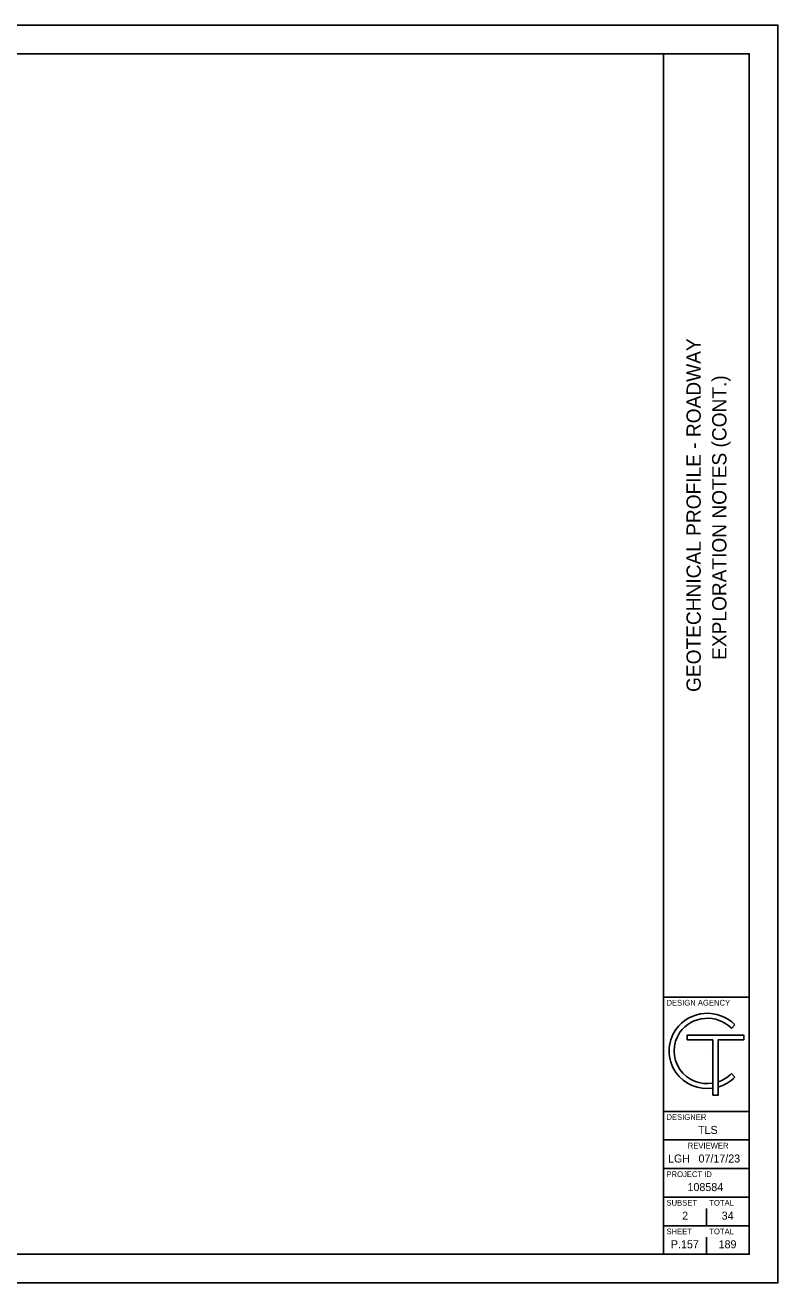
# Model space of a CAD drawing. Extents: x 0 to 34, y 0 to 22.
# Drawn here: x 20.82 to 34, y 0 to 22 of the extents above; entities that cross this region are included whole.
import ezdxf

# ---------------------------------------------------------------- set-up
doc = ezdxf.new("R2010")
doc.units = 0
for name, color, linetype in [('SH_Border', 7, 'Continuous'), ('SH_Cut_Line', 7, 'Continuous'), ('SH_Data', 7, 'Continuous'), ('SH_Text', 7, 'Continuous')]:
    doc.layers.add(name, color=color, linetype=linetype)

msp = doc.modelspace()

# ---------------------------------------------------------------- linework, layer by layer
at = {"layer": 'SH_Border'}
for p, q in [((32, 0.5), (32, 21.5)), ((32, 5), (33.5, 5)), ((32, 3), (33.5, 3)), ((32, 2.5), (33.5, 2.5)), ((32, 2), (33.5, 2)), ((32, 1.5), (33.5, 1.5)), ((32, 1), (33.5, 1))]:
    msp.add_line(p, q, dxfattribs=at)
msp.add_lwpolyline([(1.5, 21.5), (33.5, 21.5), (33.5, 0.5), (1.5, 0.5)], close=True, dxfattribs=at)
at = {"layer": 'SH_Cut_Line'}
msp.add_lwpolyline([(0, 0), (34, 0), (34, 22), (0, 22)], close=True, dxfattribs=at)
at = {"layer": 'SH_Data'}
for p, q in [((32.75, 4), (32.75, 4)), ((32.75, 1), (32.75, 1.3)), ((32.375, 0.675), (32.375, 0.675)), ((32.75, 0.5), (32.75, 0.8))]:
    msp.add_line(p, q, dxfattribs=at)
at = {"layer": 'SH_Text'}
for p, q in [((33.249, 4.513), (33.187, 4.452)), ((33.249, 4.513), (33.187, 4.452)), ((33.402, 4.333), (32.414, 4.333)), ((32.414, 4.333), (32.414, 4.251)), ((32.414, 4.251), (32.863, 4.251)), ((32.863, 4.251), (32.863, 3.285)), ((32.956, 3.285), (32.956, 4.251)), ((32.956, 4.251), (33.402, 4.251)), ((33.402, 4.251), (33.402, 4.333)), ((33.187, 3.66), (33.249, 3.599)), ((33.187, 3.66), (33.249, 3.599)), ((32.863, 3.493), (32.863, 3.405)), ((32.863, 3.493), (32.863, 3.405)), ((32.956, 3.425), (32.956, 3.516)), ((32.956, 3.425), (32.956, 3.516)), ((32.863, 3.285), (32.956, 3.285))]:
    msp.add_line(p, q, dxfattribs=at)
msp.add_lwpolyline([(32.863, 4.251), (32.863, 3.285), (32.956, 3.285), (32.956, 4.251), (33.402, 4.251), (33.402, 4.333), (32.414, 4.333), (32.414, 4.251)], close=True, dxfattribs=at)
for centre, radius, start, end in [((32.766, 4.035), 0.68, 44.7027, 144.3276), ((32.766, 4.035), 0.68, 44.7027, 144.3276), ((32.766, 4.035), 0.593, 44.7362, 144.1102), ((32.766, 4.035), 0.593, 44.7362, 144.1102), ((32.764, 4.056), 0.666, 145.7329, 214.2671), ((32.764, 4.056), 0.666, 145.7329, 214.2671), ((32.764, 4.056), 0.579, 145.7266, 214.2734), ((32.764, 4.056), 0.579, 145.7266, 214.2734), ((32.766, 4.078), 0.68, 215.6724, 278.2613), ((32.766, 4.078), 0.68, 215.6724, 278.2613), ((32.766, 4.078), 0.593, 215.8898, 279.4882), ((32.766, 4.078), 0.593, 215.8898, 279.4882), ((32.766, 4.078), 0.593, 288.6992, 315.2638), ((32.766, 4.078), 0.593, 288.6992, 315.2638), ((32.766, 4.078), 0.68, 286.2291, 315.2973), ((32.766, 4.078), 0.68, 286.2291, 315.2973)]:
    msp.add_arc(centre, radius, start, end, dxfattribs=at)

# ---------------------------------------------------------------- texts
at = {"layer": 'SH_Data'}
for s, p in [('GEOTECHNICAL PROFILE - ROADWAY', (32.65, 10.336)), ('EXPLORATION NOTES (CONT.)', (33.1, 10.897))]:
    msp.add_text(s, height=0.25, rotation=90, dxfattribs=at).set_placement(p)
for s, height, p in [('DESIGN AGENCY', 0.1, (32.05, 4.85)), ('DESIGNER', 0.1, (32.05, 2.85)), ('TLS', 0.14, (32.603, 2.605)), ('REVIEWER', 0.1, (32.422, 2.35)), ('LGH', 0.14, (32.077, 2.105)), ('07/17/23', 0.14, (32.611, 2.105)), ('PROJECT ID', 0.1, (32.05, 1.85)), ('108584', 0.14, (32.418, 1.605)), ('SUBSET', 0.1, (32.05, 1.35)), ('TOTAL', 0.1, (32.8, 1.35)), ('2', 0.14, (32.325, 1.105)), ('34', 0.14, (33.016, 1.105)), ('SHEET', 0.1, (32.05, 0.85)), ('TOTAL', 0.1, (32.8, 0.85)), ('P.157', 0.14, (32.128, 0.605)), ('189', 0.14, (32.963, 0.605))]:
    msp.add_text(s, height=height, dxfattribs=at).set_placement(p)

doc.saveas('drawing.dxf')
